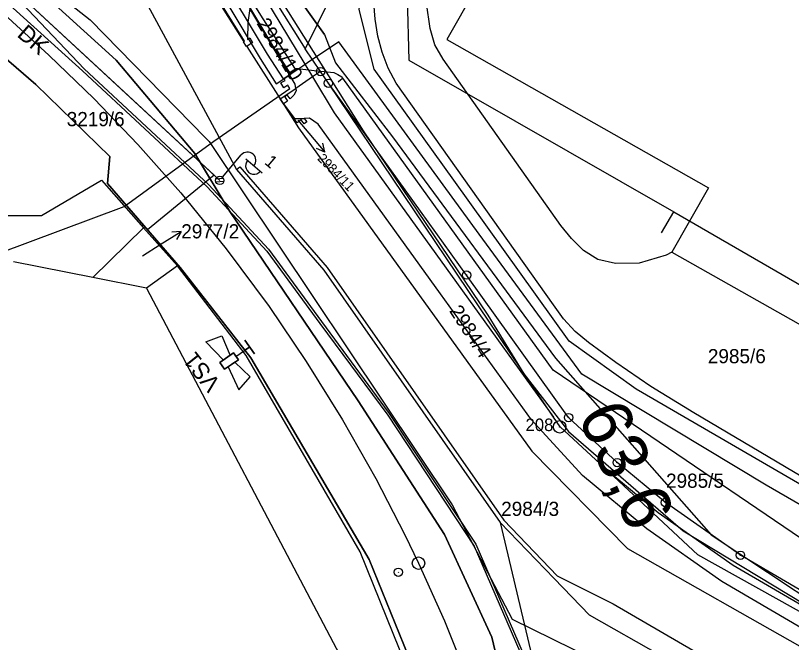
# Model space of a CAD drawing. Extents: x -620475 to -619963, y -1123010 to -1122510.
# Drawn here: x -620201.4 to -620108.2, y -1122830.6 to -1122755.4 of the extents above; entities that cross this region are included whole.
import ezdxf

# ---------------------------------------------------------------- set-up
doc = ezdxf.new("R2010")
doc.units = 0
for name, color, linetype in [('060603_ROZVODY_NN', 7, 'Continuous'), ('060604_ROZVODY_SEE', 7, 'Continuous'), ('CETIN', 7, 'Continuous'), ('GasNet', 7, 'Continuous'), ('HranDP', 7, 'Continuous'), ('Hranice parcel', 7, 'Continuous'), ('Parcelní čísla', 7, 'Continuous'), ('Pop  PČ popisy', 7, 'Continuous'), ('PS 06-14-01_trasa_sdělovací_nové', 7, 'Continuous'), ('SEE', 7, 'Continuous'), ('SSZT', 7, 'Continuous'), ('SSZT-DK', 7, 'Continuous'), ('SSZT-TK', 7, 'Continuous'), ('STÁVAJÍCÍ STOŽÁRY ODHAD', 7, 'Continuous'), ('UZEMNĚNÍ', 7, 'Continuous'), ('VAS stoka', 7, 'Continuous'), ('VAS vodovod', 7, 'Continuous'), ('Vnitřní kresba', 7, 'Continuous'), ('Vrstva 1', 7, 'Continuous'), ('Vrstva 2', 7, 'Continuous'), ('Vrstva 3', 7, 'Continuous'), ('Vrstva 7', 7, 'Continuous'), ('Věcná břemena k části', 7, 'Continuous'), ('Značky bodu BP', 7, 'Continuous'), ('ČD-T', 7, 'Continuous')]:
    doc.layers.add(name, color=color, linetype=linetype)

msp = doc.modelspace()

# ---------------------------------------------------------------- linework, layer by layer
at = {"layer": '060603_ROZVODY_NN'}
msp.add_lwpolyline([(-620240.174, -1122718.342), (-620228.339, -1122728.069), (-620221.166, -1122735.76), (-620213.633, -1122742.038), (-620205.954, -1122748.188), (-620177.512, -1122774.524), (-620185.522, -1122781.049), (-620181.59, -1122785.57), (-620173.131, -1122796.401), (-620158.909, -1122820.61), (-620151.64, -1122838.53), (-620148.846, -1122845.743), (-620146.967, -1122851.788), (-620142.651, -1122873.562), (-620132.315, -1122871.722), (-620130.544, -1122883.681), (-620130.195, -1122888.406), (-620130.037, -1122888.394)], dxfattribs=at)
at = {"layer": '060604_ROZVODY_SEE'}
msp.add_lwpolyline([(-620176.843, -1122775.143), (-620205.954, -1122748.188), (-620213.633, -1122742.038), (-620221.166, -1122735.76), (-620228.339, -1122728.069), (-620234.256, -1122723.205), (-620240.174, -1122718.342), (-620248.298, -1122711.665), (-620253.571, -1122707.331), (-620257.271, -1122704.364), (-620247.325, -1122692.032), (-620244.518, -1122694.296)], dxfattribs=at)
at = {"layer": 'CETIN'}
for points in [[(-620322.39, -1122622.262), (-620301.06, -1122636.75), (-620273.539, -1122652.218), (-620253.246, -1122663.163), (-620204.022, -1122698.845), (-620159.643, -1122769.192), (-620144.669, -1122791.286), (-620140.333, -1122798.335), (-620134.98, -1122805.248), (-620121.226, -1122817.175), (-620095.953, -1122832.424), (-620068.004, -1122848.181)], [(-620227.04, -1122727.67), (-620227.6, -1122728.26), (-620225.24, -1122730.07), (-620192.39, -1122755.87), (-620182.03, -1122766.47), (-620178.55, -1122770.03), (-620178.11, -1122770.48), (-620148.97, -1122814.05), (-620141.74, -1122827.78), (-620093.42, -1122851.53), (-620088.91, -1122854.99)], [(-620170.944, -1122748.28), (-620164.261, -1122757.63)], [(-620164.261, -1122757.63), (-620170.944, -1122748.28)], [(-620164.261, -1122757.63), (-620162.95, -1122761.03), (-620156.11, -1122769.9), (-620136.563, -1122796.46), (-620117.888, -1122817.631), (-620104.34, -1122826.6), (-620099.09, -1122828.81), (-620092.09, -1122832.08), (-620086.33, -1122833.54), (-620081.024, -1122834.312)], [(-620178.55, -1122770.03), (-620182.03, -1122766.47)]]:
    msp.add_lwpolyline(points, dxfattribs=at)
at = {"layer": 'GasNet'}
for points in [[(-620169.189, -1122762.97), (-620171.1, -1122759.99), (-620177.21, -1122749.83), (-620183.11, -1122739.88), (-620187.41, -1122733.49), (-620188.174, -1122734.038)], [(-620046.14, -1122851.29), (-620053.62, -1122841.38), (-620061.16, -1122831.41), (-620068.48, -1122836.5), (-620088.2, -1122824.99), (-620093.656, -1122821.845), (-620093.89, -1122821.71), (-620111.26, -1122811.68), (-620133.38, -1122798.37), (-620145.72, -1122781.6), (-620162.54, -1122758.52), (-620166.304, -1122761.04), (-620166.886, -1122761.429), (-620167.468, -1122761.818), (-620169.13, -1122762.93), (-620169.189, -1122762.97)], [(-620203.57, -1122783.96), (-620188.33, -1122778.28), (-620177.56, -1122770.44), (-620168.45, -1122764.1), (-620168.625, -1122763.792), (-620168.66, -1122763.73), (-620169.16, -1122764.02), (-620169.5, -1122763.44), (-620169.25, -1122763.27)], [(-620169.25, -1122763.27), (-620169, -1122763.15), (-620169.13, -1122762.93)]]:
    msp.add_lwpolyline(points, dxfattribs=at)
at = {"layer": 'HranDP'}
msp.add_line((-620185.98, -1122780.81), (-620181.92, -1122785.4), dxfattribs=at)
for points in [[(-620197.33, -1122735.44), (-620187.9, -1122749.66), (-620174.83, -1122773.82), (-620164.34, -1122785.91), (-620143.18, -1122816.17)], [(-620224.92, -1122769.84), (-620205.84, -1122779.33), (-620198.25, -1122779.35), (-620191.03, -1122775.11), (-620185.98, -1122780.81)], [(-620152.84, -1122837.4), (-620159.98, -1122819.68), (-620173.68, -1122796.12), (-620181.92, -1122785.4)], [(-620143.18, -1122816.17), (-620134.66, -1122852.11), (-620129.18, -1122882.66), (-620128.4, -1122892.9)]]:
    msp.add_lwpolyline(points, dxfattribs=at)
at = {"layer": 'Hranice parcel'}
for p, q in [((-620152.03, -1122729.88), (-620166.6, -1122759.34)), ((-620171.74, -1122751.13), (-620166.6, -1122759.34)), ((-620164.75, -1122762.08), (-620166.6, -1122759.34)), ((-620163.81, -1122763.48), (-620164.75, -1122762.08)), ((-620192.09, -1122786.79), (-620185.98, -1122780.81)), ((-620185.98, -1122780.81), (-620181.92, -1122785.4)), ((-620192.09, -1122786.79), (-620201.6, -1122784.9))]:
    msp.add_line(p, q, dxfattribs=at)
for points in [[(-620129.52, -1122710.96), (-620130.02, -1122711.91), (-620134.59, -1122719.84), (-620129.48, -1122722.79), (-620130.16, -1122724), (-620132.92, -1122728.86), (-620133.58, -1122730.02), (-620135.85, -1122734.02), (-620141.6, -1122730.74), (-620148.58, -1122743.04), (-620142.8, -1122746.27), (-620149.58, -1122758.23), (-620118.17, -1122776.02), (-620122.58, -1122783.75), (-620090.7, -1122801.75)], [(-620027.34, -1122787.19), (-620029.12, -1122790.47), (-620030.63, -1122793.23), (-620030.93, -1122793.08), (-620062.93, -1122815.9), (-620079.47, -1122827.69), (-620107.97, -1122811.15), (-620126.88, -1122800.18), (-620134.93, -1122794.41), (-620148.77, -1122775.1), (-620158.3, -1122761.8), (-620160.13, -1122754.62), (-620158.82, -1122744.94), (-620155.87, -1122738.11), (-620144.37, -1122714.62)], [(-620197.33, -1122735.44), (-620187.9, -1122749.66), (-620174.83, -1122773.82), (-620164.34, -1122785.91), (-620143.18, -1122816.17)], [(-620173.24, -1122754.52), (-620173.48, -1122756.2), (-620173.53, -1122758.23), (-620173.22, -1122758.03), (-620172.91, -1122758.59), (-620173.61, -1122759.06), (-620173.64, -1122759.08), (-620174, -1122758.53), (-620173.96, -1122758.5), (-620173.87, -1122758.44), (-620183.92, -1122742.28), (-620184.05, -1122742.35), (-620184.39, -1122741.79), (-620183.63, -1122741.31), (-620183.27, -1122741.89), (-620183.57, -1122742.07), (-620182.08, -1122742.82), (-620180.68, -1122743.31), (-620179.21, -1122743.55), (-620177.73, -1122743.55), (-620176.62, -1122743.36)], [(-620167.73, -1122764.1), (-620167.81, -1122763.6), (-620173.24, -1122754.52)], [(-620164.75, -1122762.08), (-620165.7, -1122762.73), (-620167.73, -1122764.1)], [(-620072.47, -1122846.25), (-620119.48, -1122820.03), (-620130.17, -1122810.08), (-620136, -1122804.68), (-620136.79, -1122803.52), (-620163.81, -1122763.48)], [(-620069.79, -1122845.77), (-620093.24, -1122832.45), (-620114.36, -1122820.1), (-620123.37, -1122813.77), (-620129.15, -1122808.98), (-620134.98, -1122803.58), (-620147.22, -1122786.5), (-620163.81, -1122763.48)], [(-620169.18, -1122765.95), (-620169.61, -1122765.37), (-620167.73, -1122764.1)], [(-620169.18, -1122765.95), (-620167.86, -1122767.72), (-620166.7, -1122767.69)], [(-620166.7, -1122767.69), (-620166.41, -1122768.09), (-620166.72, -1122768.33), (-620167.06, -1122767.87), (-620167.55, -1122768.23), (-620169.18, -1122765.95)], [(-620074.02, -1122848.16), (-620095.17, -1122835.78), (-620116.57, -1122823.25), (-620125.58, -1122816.92), (-620133.3, -1122810.53), (-620139.43, -1122803.84), (-620150.35, -1122788.75), (-620165.02, -1122768.39), (-620166.09, -1122767.67), (-620166.7, -1122767.69)], [(-620224.92, -1122769.84), (-620205.84, -1122779.33), (-620198.25, -1122779.35), (-620191.03, -1122775.11), (-620185.98, -1122780.81)], [(-620181.92, -1122785.4), (-620185.65, -1122788.07), (-620192.09, -1122786.79)], [(-620152.84, -1122837.4), (-620159.98, -1122819.68), (-620173.68, -1122796.12), (-620181.92, -1122785.4)], [(-620143.18, -1122816.17), (-620134.66, -1122852.11), (-620129.18, -1122882.66), (-620128.4, -1122892.9)], [(-620080.86, -1122856.55), (-620132.47, -1122827.27), (-620136.72, -1122822.9), (-620143.18, -1122816.17)]]:
    msp.add_lwpolyline(points, dxfattribs=at)
at = {"layer": 'Pop  PČ popisy'}
for p, q in [((-620167.46, -1122767.92), (-620166.15, -1122769.46)), ((-620166.15, -1122769.46), (-620164.221, -1122771.759)), ((-620164.221, -1122771.759), (-620164.481, -1122770.67)), ((-620164.221, -1122771.759), (-620165.248, -1122771.314)), ((-620184.01, -1122782.84), (-620181.465, -1122781.25)), ((-620181.465, -1122781.25), (-620182.58, -1122781.356)), ((-620181.465, -1122781.25), (-620182.049, -1122782.205)), ((-620186.13, -1122784.19), (-620184.01, -1122782.84))]:
    msp.add_line(p, q, dxfattribs=at)
at = {"layer": 'PS 06-14-01_trasa_sdělovací_nové'}
msp.add_lwpolyline([(-620232.134, -1122718.841), (-620235.045, -1122722.562), (-620243.025, -1122715.998), (-620248.321, -1122722.765), (-620228.504, -1122738.508), (-620211.634, -1122752.654), (-620198.933, -1122763.626), (-620190.05, -1122772.28), (-620190.33, -1122775.52), (-620181.59, -1122785.57), (-620173.131, -1122796.401), (-620158.909, -1122820.61), (-620151.64, -1122838.53)], dxfattribs=at)
at = {"layer": 'SEE'}
msp.add_lwpolyline([(-620257.826, -1122706.644), (-620244.955, -1122716.952), (-620221.313, -1122735.887), (-620205.954, -1122748.188), (-620187.818, -1122764.98), (-620176.843, -1122775.143)], dxfattribs=at)
at = {"layer": 'SSZT'}
msp.add_lwpolyline([(-620131.713, -1122887.843), (-620132.103, -1122876.02), (-620140.705, -1122844.513), (-620144.18, -1122829.908), (-620149.89, -1122817.622), (-620160.216, -1122801.593), (-620175.654, -1122778.856), (-620179.825, -1122771.902), (-620189.291, -1122760.708), (-620207.424, -1122744.252), (-620237.066, -1122720.469), (-620255.602, -1122705.516), (-620251.355, -1122700.201)], dxfattribs=at)
at = {"layer": 'SSZT-DK'}
msp.add_lwpolyline([(-620400.12, -1122648.456), (-620392.309, -1122655.212), (-620359.04, -1122685.798), (-620308.772, -1122717.798), (-620291.405, -1122732.208), (-620277.196, -1122744.115), (-620257.608, -1122720.05), (-620250.251, -1122710.721), (-620233.29, -1122724.26), (-620218.699, -1122737.685), (-620210.438, -1122746.518), (-620193.319, -1122761.993), (-620178.352, -1122775.894), (-620171.184, -1122783.621), (-620164.843, -1122792.284), (-620156.695, -1122803.312), (-620146.306, -1122818.994), (-620117.638, -1122885.131), (-620110.298, -1122902.137)], dxfattribs=at)
at = {"layer": 'SSZT-TK'}
msp.add_lwpolyline([(-620251.547, -1122700.3), (-620255.602, -1122705.516), (-620237.066, -1122720.469), (-620207.424, -1122744.252), (-620189.291, -1122760.708), (-620179.825, -1122771.902), (-620175.654, -1122778.856), (-620160.216, -1122801.593), (-620149.89, -1122817.622), (-620144.18, -1122829.908), (-620140.705, -1122844.513), (-620132.103, -1122876.02), (-620131.713, -1122886.934), (-620131.713, -1122887.843), (-620128.502, -1122887.822), (-620131.713, -1122887.843), (-620131.713, -1122914.315), (-620136.813, -1122914.315), (-620139.347, -1122912.91)], dxfattribs=at)
at = {"layer": 'STÁVAJÍCÍ STOŽÁRY ODHAD'}
for p, q in [((-620176.528, -1122774.758), (-620174.266, -1122772.087)), ((-620173.732, -1122772.539), (-620171.748, -1122774.219)), ((-620177.316, -1122775.319), (-620176.362, -1122775.24)), ((-620177.31, -1122774.942), (-620176.434, -1122774.869))]:
    msp.add_line(p, q, dxfattribs=at)
msp.add_circle((-620176.851, -1122775.14), 0.5, dxfattribs=at)
for centre, start, end in [((-620173.503, -1122772.733), 319.74828, 139.74828), ((-620172.748, -1122773.389), 139.04571, 320.45085)]:
    msp.add_arc(centre, 1, start, end, dxfattribs=at)
at = {"layer": 'UZEMNĚNÍ'}
msp.add_lwpolyline([(-620221.747, -1122750.368), (-620214.46, -1122741.375), (-620205.954, -1122748.188), (-620176.843, -1122775.143)], dxfattribs=at)
at = {"layer": 'VAS stoka'}
for p, q in [((-620154.6, -1122743.36), (-620154.17, -1122760.72)), ((-620154.17, -1122760.72), (-620122.365, -1122778.921)), ((-620123.82, -1122781.44), (-620122.365, -1122778.921)), ((-620122.365, -1122778.921), (-620079.029, -1122803.959))]:
    msp.add_line(p, q, dxfattribs=at)
at = {"layer": 'VAS vodovod'}
for points in [[(-620187.76, -1122731.9), (-620187.61, -1122732.165), (-620187.46, -1122732.43), (-620186.51, -1122732.96), (-620185.56, -1122733.49), (-620182.395, -1122738.6), (-620179.23, -1122743.71), (-620175.45, -1122749.725), (-620171.67, -1122755.74), (-620169.77, -1122758.715), (-620167.87, -1122761.69), (-620165.505, -1122761.94), (-620163.14, -1122762.19), (-620162.665, -1122762.45), (-620162.19, -1122762.71)], [(-620162.62, -1122763.32), (-620162.32, -1122763.04), (-620162.059, -1122762.891)], [(-620094.32, -1122826.78), (-620136.84, -1122797.89), (-620162.059, -1122762.891), (-620162.19, -1122762.71)]]:
    msp.add_lwpolyline(points, dxfattribs=at)
at = {"layer": 'Vnitřní kresba'}
for p, q in [((-620191.31, -1122731.11), (-620173.96, -1122758.5)), ((-620172.25, -1122751.89), (-620165.7, -1122762.73)), ((-620158.2, -1122755.8), (-620158.37, -1122753.78)), ((-620151.58, -1122756.91), (-620152.03, -1122753.86)), ((-620157.86, -1122757.82), (-620158.2, -1122755.8)), ((-620151.04, -1122758.86), (-620151.58, -1122756.91)), ((-620157.34, -1122759.76), (-620157.86, -1122757.82)), ((-620150.03, -1122760.6), (-620151.04, -1122758.86)), ((-620173.61, -1122759.06), (-620169.61, -1122765.37)), ((-620156.64, -1122761.69), (-620157.34, -1122759.76)), ((-620135.93, -1122780.56), (-620150.03, -1122760.6)), ((-620155.67, -1122763.48), (-620156.64, -1122761.69)), ((-620165.7, -1122762.73), (-620163.11, -1122767.02)), ((-620136.78, -1122790.07), (-620155.67, -1122763.48)), ((-620167.68, -1122764.39), (-620167.95, -1122764.93)), ((-620167.73, -1122764.1), (-620167.68, -1122764.39)), ((-620169.61, -1122765.37), (-620167.41, -1122768.84)), ((-620168.75, -1122764.87), (-620169.05, -1122765.1)), ((-620169.05, -1122765.1), (-620168.7, -1122765.62)), ((-620168.38, -1122765.37), (-620168.75, -1122764.87)), ((-620167.95, -1122764.93), (-620168.38, -1122765.37)), ((-620168.7, -1122765.62), (-620169.18, -1122765.95)), ((-620163.11, -1122767.02), (-620148.44, -1122787.38)), ((-620167.41, -1122768.84), (-620139.39, -1122807.63)), ((-620174.83, -1122773.82), (-620174.45, -1122773.49)), ((-620174.45, -1122773.49), (-620163.96, -1122785.58)), ((-620134.64, -1122782.1), (-620135.93, -1122780.56)), ((-620133.21, -1122783.55), (-620134.64, -1122782.1)), ((-620131.49, -1122784.61), (-620133.21, -1122783.55)), ((-620163.96, -1122785.58), (-620142.77, -1122815.89)), ((-620148.44, -1122787.38), (-620136.79, -1122803.52)), ((-620185.65, -1122788.07), (-620157.72, -1122840.99)), ((-620135.58, -1122791.72), (-620136.78, -1122790.07)), ((-620134.2, -1122793.25), (-620135.58, -1122791.72)), ((-620132.61, -1122794.57), (-620134.2, -1122793.25)), ((-620129.33, -1122796.98), (-620132.61, -1122794.57)), ((-620125.13, -1122799.85), (-620129.33, -1122796.98)), ((-620119.93, -1122803.03), (-620125.13, -1122799.85)), ((-620104.17, -1122812.35), (-620119.93, -1122803.03)), ((-620139.39, -1122807.63), (-620127.92, -1122819.29)), ((-620124.23, -1122815), (-620130.17, -1122810.08)), ((-620115.22, -1122821.33), (-620124.23, -1122815)), ((-620142.77, -1122815.89), (-620136.36, -1122822.55)), ((-620127.92, -1122819.29), (-620075.39, -1122849.03)), ((-620093.98, -1122833.75), (-620115.22, -1122821.33)), ((-620136.36, -1122822.55), (-620129.64, -1122825.94)), ((-620129.64, -1122825.94), (-620104.21, -1122840.64))]:
    msp.add_line(p, q, dxfattribs=at)
msp.add_lwpolyline([(-620122.58, -1122783.75), (-620123.27, -1122784.1), (-620126.53, -1122785.08), (-620129.37, -1122785.1), (-620131.49, -1122784.61)], dxfattribs=at)
at = {"layer": 'Vrstva 1'}
msp.add_line((-620173.253, -1122795.11), (-620173.839, -1122795.494), dxfattribs=at)
for points in [[(-620173.839, -1122795.494), (-620176.67, -1122791.87), (-620181.59, -1122785.57), (-620185.43, -1122781.13), (-620190.33, -1122775.52), (-620190.05, -1122772.28), (-620198.933, -1122763.626), (-620211.634, -1122752.654), (-620228.504, -1122738.508), (-620248.321, -1122722.765)], [(-620203.242, -1122754.772), (-620197.369, -1122760.098), (-620191.907, -1122765.364), (-620186.688, -1122770.813), (-620182.207, -1122775.852), (-620181.539, -1122776.643), (-620176.088, -1122783.334), (-620170.93, -1122790.268), (-620166.464, -1122796.851), (-620162.113, -1122803.839), (-620158.128, -1122810.876), (-620154.628, -1122817.641), (-620152.992, -1122821.05), (-620149.889, -1122827.962), (-620146.963, -1122835.3)], [(-620151.284, -1122839.448), (-620151.64, -1122838.53), (-620158.909, -1122820.61), (-620164.59, -1122810.94), (-620173.131, -1122796.401), (-620173.839, -1122795.494)]]:
    msp.add_lwpolyline(points, dxfattribs=at)
at = {"layer": 'Vrstva 2'}
for p, q in [((-620172.685, -1122795.933), (-620173.822, -1122794.288)), ((-620173.822, -1122794.288), (-620172.685, -1122795.933)), ((-620174.899, -1122796.247), (-620173.253, -1122795.11)), ((-620174.899, -1122796.247), (-620173.253, -1122795.11))]:
    msp.add_line(p, q, dxfattribs=at)
for points in [[(-620176.417, -1122796.689), (-620178.534, -1122794.505), (-620176.604, -1122793.779), (-620175.594, -1122796.12)], [(-620176.26, -1122797.795), (-620176.828, -1122796.973), (-620175.183, -1122795.836), (-620174.614, -1122796.659)], [(-620176.828, -1122796.973), (-620176.26, -1122797.795), (-620174.614, -1122796.659), (-620175.183, -1122795.836)], [(-620175.848, -1122797.511), (-620174.554, -1122800.264), (-620173.193, -1122798.715), (-620175.026, -1122796.943)]]:
    msp.add_lwpolyline(points, close=True, dxfattribs=at)
at = {"layer": 'Vrstva 7'}
msp.add_line((-620155.437, -1122822.091), (-620155.397, -1122822.183), dxfattribs=at)
for centre, radius in [((-620152.992, -1122821.05), 0.75), ((-620155.417, -1122822.137), 0.5)]:
    msp.add_circle(centre, radius, dxfattribs=at)
at = {"layer": 'Věcná břemena k části'}
msp.add_lwpolyline([(-620187.14, -1122731.99), (-620188.79, -1122733.18), (-620187.68, -1122734.99), (-620184.01, -1122740.44), (-620172.01, -1122760.53), (-620170.08, -1122763.54), (-620168.3, -1122762.4), (-620170.19, -1122759.45), (-620182.21, -1122739.32)], close=True, dxfattribs=at)
at = {"layer": 'Značky bodu BP'}
for centre, radius in [((-620164.75, -1122762.08), 0.5), ((-620164.75, -1122762.08), 0.0303), ((-620163.81, -1122763.48), 0.5), ((-620163.81, -1122763.48), 0.0303), ((-620147.22, -1122786.5), 0.5), ((-620147.22, -1122786.5), 0.0303), ((-620134.98, -1122803.58), 0.5), ((-620134.98, -1122803.58), 0.0303), ((-620136.05, -1122804.7), 0.75), ((-620136.05, -1122804.7), 0.03), ((-620129.15, -1122808.98), 0.5), ((-620129.15, -1122808.98), 0.0303), ((-620123.37, -1122813.77), 0.5), ((-620123.37, -1122813.77), 0.0303), ((-620114.36, -1122820.1), 0.5), ((-620114.36, -1122820.1), 0.0303)]:
    msp.add_circle(centre, radius, dxfattribs=at)
at = {"layer": 'ČD-T'}
msp.add_lwpolyline([(-620399.923, -1122648.231), (-620392.122, -1122654.977), (-620358.852, -1122685.564), (-620308.585, -1122717.564), (-620291.218, -1122731.973), (-620279.983, -1122741.462), (-620260.482, -1122717.473), (-620252.938, -1122708.192), (-620233.103, -1122724.025), (-620218.511, -1122737.45), (-620206.638, -1122747.527), (-620193.132, -1122761.758), (-620178.165, -1122775.66), (-620170.996, -1122783.386), (-620164.655, -1122792.049), (-620156.507, -1122803.078), (-620146.119, -1122818.76), (-620117.451, -1122884.896), (-620110.11, -1122901.903)], dxfattribs=at)

# ---------------------------------------------------------------- texts
at = {"layer": 'Parcelní čísla'}
for s, height, rotation, p in [('2984/10', 1.7, 301, (-620172.471, -1122756.289)), ('2984/11', 1.139, 314, (-620165.205, -1122772.575)), ('2984/4', 1.7, 303, (-620149.362, -1122790.782))]:
    msp.add_text(s, height=height, rotation=rotation, dxfattribs=at).set_placement(p)
for s, p in [('3219/6', (-620195.215, -1122768.63)), ('2977/2', (-620181.47, -1122782.09)), ('2985/6', (-620118.265, -1122797.066)), ('2985/5', (-620123.285, -1122812.006)), ('2984/3', (-620143.07, -1122815.38))]:
    msp.add_text(s, height=1.7, dxfattribs=at).set_placement(p)
at = {"layer": 'SSZT-DK'}
msp.add_text('DK', height=2, rotation=319.15653, dxfattribs=at).set_placement((-620201.286, -1122757.79))
at = {"layer": 'STÁVAJÍCÍ STOŽÁRY ODHAD'}
msp.add_text('1', height=1.5, rotation=319.74828, dxfattribs=at).set_placement((-620171.572, -1122773.08))
at = {"layer": 'Vrstva 3'}
msp.add_text('VS1', height=2, rotation=128.54201, dxfattribs=at).set_placement((-620176.647, -1122799.482))
at = {"layer": 'Vrstva 7'}
msp.add_text('63,6', height=6, rotation=294.17671, dxfattribs=at).set_placement((-620133.968, -1122803.316))
at = {"layer": 'Značky bodu BP'}
msp.add_text('208', height=1.5, dxfattribs=at).set_placement((-620140.153, -1122805.2))

doc.saveas('drawing.dxf')
